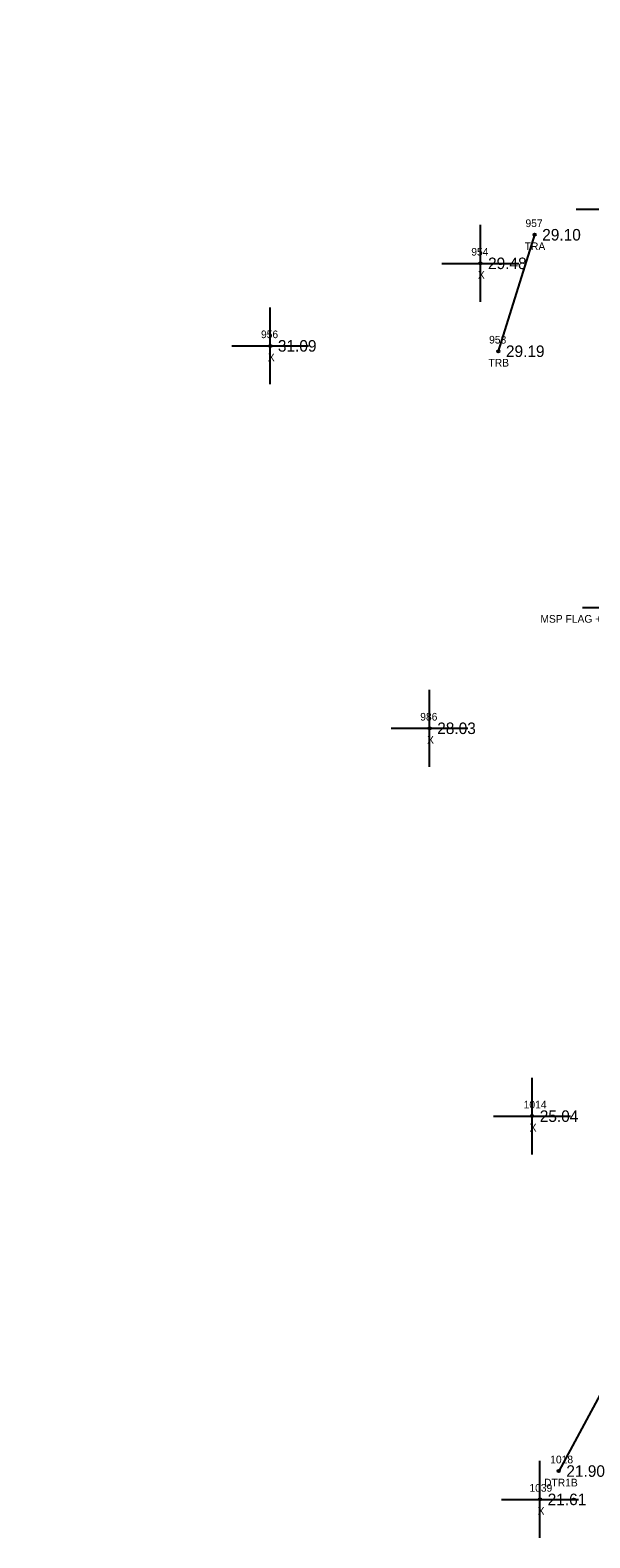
# Model space of a CAD drawing. Extents: x 2042211 to 2045853, y 303080 to 309569.
# Drawn here: x 2042788.5 to 2042861.3, y 306604 to 306800.2 of the extents above; entities that cross this region are included whole.
import ezdxf

# ---------------------------------------------------------------- set-up
doc = ezdxf.new("R2010")
doc.units = 0
for name, color, linetype in [('BR_500YR_SCOUR', 7, 'Continuous'), ('RD_EX_H2O', 7, 'Continuous'), ('RD_EX_H2O_txCode', 7, 'Continuous'), ('RD_EX_Misc', 7, 'Continuous'), ('RD_EX_Misc_txCode', 7, 'Continuous'), ('RD_EX_TX_H2O_ELEV', 7, 'Continuous'), ('RD_EX_TX_Misc_ELEV', 7, 'Continuous'), ('RD_EX_TX_VEG_ELEV', 7, 'Continuous'), ('RD_EX_VEG_txCode', 7, 'Continuous'), ('RD_SMD_Locator', 7, 'Continuous')]:
    doc.layers.add(name, color=color, linetype=linetype)

msp = doc.modelspace()

# ---------------------------------------------------------------- linework, layer by layer
at = {"layer": 'BR_500YR_SCOUR'}
msp.add_line((2042854.11, 306773.62), (2042849.39, 306758.46), dxfattribs=at)
for centre in [(2042854.11, 306773.62), (2042849.39, 306758.46)]:
    msp.add_circle(centre, 0.15, dxfattribs=at)
at = {"layer": 'RD_EX_H2O'}
msp.add_lwpolyline([(2042809.74, 307126.16), (2042806.56, 307122.63), (2042790.31, 307116.78), (2042788.49, 307114.78), (2042791.89, 307113.57), (2042804.81, 307114.94), (2042810.25, 307075.93), (2042820.25, 307025.92), (2042830.4, 306977.21), (2042843.29, 306928.12), (2042852.91, 306878.24), (2042864.55, 306828.43), (2042879.23, 306781.72), (2042889.45, 306748.73), (2042886.16, 306741.98), (2042888.34, 306727.94), (2042896.13, 306676.35), (2042885.67, 306665.43), (2042857.25, 306612.72)], dxfattribs=at)
at = {"layer": 'RD_EX_Misc'}
for p, q in [((2042859.51, 306776.94), (2042869.51, 306776.94)), ((2042847.06, 306764.9), (2042847.06, 306774.9)), ((2042842.06, 306769.9), (2042852.06, 306769.9)), ((2042819.72, 306754.16), (2042819.72, 306764.16)), ((2042814.72, 306759.16), (2042824.72, 306759.16)), ((2042860.36, 306725.13), (2042870.36, 306725.13)), ((2042840.45, 306704.39), (2042840.45, 306714.39)), ((2042835.45, 306709.39), (2042845.45, 306709.39)), ((2042853.79, 306653.91), (2042853.79, 306663.91)), ((2042848.79, 306658.91), (2042858.79, 306658.91)), ((2042854.82, 306604.03), (2042854.82, 306614.03)), ((2042849.82, 306609.03), (2042859.82, 306609.03))]:
    msp.add_line(p, q, dxfattribs=at)
at = {"layer": 'RD_SMD_Locator'}
for centre in [(2042847.06, 306769.9), (2042819.72, 306759.16), (2042840.45, 306709.39), (2042853.79, 306658.91), (2042857.25, 306612.72), (2042854.82, 306609.03)]:
    msp.add_circle(centre, 0.15, dxfattribs=at)

# ---------------------------------------------------------------- texts
at = {"layer": 'RD_EX_H2O_txCode'}
for s, p in [('1018', (2042856.15, 306613.72)), ('DTR1B', (2042855.35, 306610.72))]:
    msp.add_text(s, height=1, dxfattribs=at).set_placement(p)
at = {"layer": 'RD_EX_Misc_txCode'}
for s, p in [('954', (2042845.88, 306770.9)), ('X', (2042846.74, 306767.9)), ('956', (2042818.52, 306760.16)), ('X', (2042819.41, 306757.16)), ('MSP FLAG + N410 E455 FS1', (2042854.87, 306723.13)), ('986', (2042839.24, 306710.39)), ('X', (2042840.13, 306707.39)), ('1014', (2042852.69, 306659.91)), ('X', (2042853.47, 306656.91)), ('1039', (2042853.44, 306610.03)), ('X', (2042854.51, 306607.03))]:
    msp.add_text(s, height=1, dxfattribs=at).set_placement(p)
at = {"layer": 'RD_EX_TX_H2O_ELEV'}
msp.add_text('21.90', height=1.5, dxfattribs=at).set_placement((2042858.25, 306611.97))
at = {"layer": 'RD_EX_TX_Misc_ELEV'}
for s, p in [('29.48', (2042848.06, 306769.15)), ('31.09', (2042820.72, 306758.41)), ('28.03', (2042841.45, 306708.64)), ('25.04', (2042854.79, 306658.16)), ('21.61', (2042855.82, 306608.28))]:
    msp.add_text(s, height=1.5, dxfattribs=at).set_placement(p)
at = {"layer": 'RD_EX_TX_VEG_ELEV'}
for s, p in [('29.10', (2042855.11, 306772.87)), ('29.19', (2042850.39, 306757.71))]:
    msp.add_text(s, height=1.5, dxfattribs=at).set_placement(p)
at = {"layer": 'RD_EX_VEG_txCode'}
for s, p in [('957', (2042852.93, 306774.62)), ('TRA', (2042852.83, 306771.62)), ('958', (2042848.2, 306759.46)), ('TRB', (2042848.12, 306756.46))]:
    msp.add_text(s, height=1, dxfattribs=at).set_placement(p)

doc.saveas('drawing.dxf')
